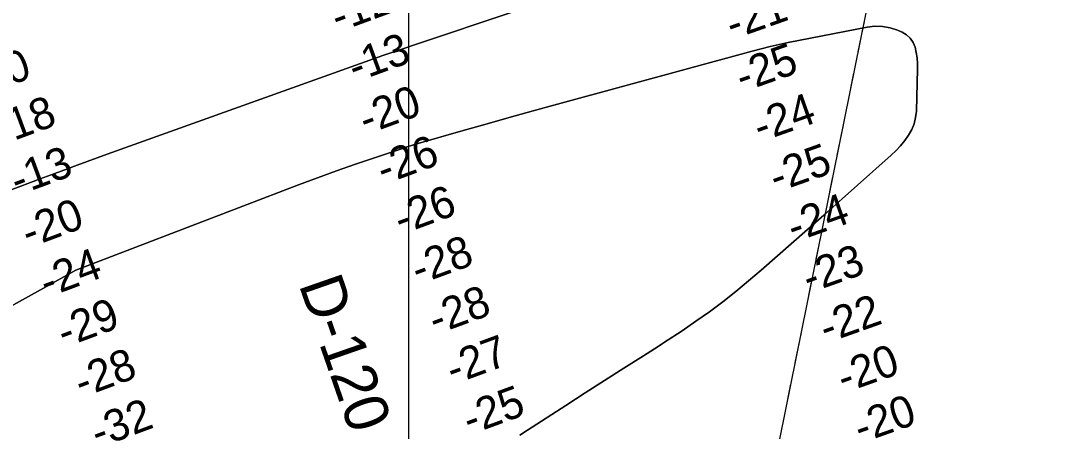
# Model space of a CAD drawing. Extents: x 3245246 to 3283090, y 806824 to 832173.
# Drawn here: x 3259157 to 3261130, y 819294 to 820069 of the extents above; entities that cross this region are included whole.
import ezdxf

# ---------------------------------------------------------------- set-up
doc = ezdxf.new("R2010")
doc.units = 0
for name, color, linetype in [('V-GRID-MAJR', 7, 'Continuous'), ('V-RIVR-FERY', 7, 'Continuous'), ('V-RIVR-RANG', 7, 'Continuous'), ('V-RIVR-RANG-IDEN', 7, 'Continuous'), ('V-TOPO-DPTH', 7, 'Continuous'), ('V-TOPO-MINR', 7, 'Continuous')]:
    doc.layers.add(name, color=color, linetype=linetype)

msp = doc.modelspace()

# ---------------------------------------------------------------- linework, layer by layer
at = {"layer": 'V-GRID-MAJR'}
msp.add_spline([(3259886.4, 812208.7), (3259889.9, 818267.9), (3259893.4, 824330.1), (3259897, 830392.4), (3259897, 830395.5)], degree=3, dxfattribs=at)
at = {"layer": 'V-RIVR-FERY'}
for points in [[(3260522.1, 818934), (3261392, 823224.9)], [(3260740.5, 820011), (3260752, 820068.2)], [(3260720.6, 819913.1), (3260732.2, 819970.3)], [(3260700.8, 819815.2), (3260712.3, 819872.4)], [(3260680.9, 819717.3), (3260692.5, 819774.4)], [(3260661.1, 819619.4), (3260672.6, 819676.5)], [(3260641.2, 819521.5), (3260652.8, 819578.6)], [(3260621.4, 819423.6), (3260632.9, 819480.7)], [(3260601.5, 819325.7), (3260613.1, 819382.8)]]:
    msp.add_lwpolyline(points, dxfattribs=at)
at = {"layer": 'V-TOPO-DPTH'}
for points in [[(3260457.7, 820210.7), (3259841.5, 820003.5), (3259320.2, 819817.3), (3259301.4, 819810.5), (3259282.6, 819803.7), (3259263.9, 819796.8), (3259245.1, 819789.8), (3259221.5, 819780.9), (3259214.6, 819778.3), (3259207.7, 819775.7), (3259200.8, 819773.2), (3259193.9, 819770.6), (3259134, 819748.5)], [(3259134, 819748.5), (3259193.9, 819770.6), (3259200.8, 819773.2), (3259207.7, 819775.7), (3259214.6, 819778.3), (3259221.5, 819780.9), (3259245.1, 819789.8), (3259263.9, 819796.8), (3259282.6, 819803.7), (3259301.4, 819810.5), (3259320.2, 819817.3), (3259841.5, 820003.5), (3260457.7, 820210.7)], [(3260838.8, 820036.6), (3260831.7, 820042.8), (3260823.2, 820047.9), (3260814.7, 820051.5), (3260800.7, 820056), (3260786.5, 820058.8), (3260772, 820059), (3260757.3, 820057.4), (3260608.1, 820028.1), (3260590.9, 820024.6), (3260573.8, 820020.8), (3260556.7, 820016.6), (3260539.8, 820012.1), (3260171.6, 819911.7), (3260125.9, 819899.1), (3260080.2, 819886.4), (3260034.6, 819873.6), (3259989, 819860.6), (3259918.9, 819840.6), (3259908.4, 819837.5), (3259897.9, 819834.3), (3259887.5, 819831.1), (3259877.1, 819827.7), (3259825.6, 819810.7), (3259789.6, 819798.5), (3259753.7, 819786), (3259718, 819773), (3259682.4, 819759.6), (3259261.3, 819598.2), (3258908.3, 819402.7)], [(3258908.3, 819402.7), (3259261.3, 819598.2), (3259682.4, 819759.6), (3259718, 819773), (3259753.7, 819786), (3259789.6, 819798.5), (3259825.6, 819810.7), (3259877.1, 819827.7), (3259887.5, 819831.1), (3259897.9, 819834.3), (3259908.4, 819837.5), (3259918.9, 819840.6), (3259989, 819860.6), (3260034.6, 819873.6), (3260080.2, 819886.4), (3260125.9, 819899.1), (3260171.6, 819911.7), (3260539.8, 820012.1), (3260556.7, 820016.6), (3260573.8, 820020.8), (3260590.9, 820024.6), (3260608.1, 820028.1), (3260757.3, 820057.4), (3260772, 820059), (3260786.5, 820058.8), (3260800.7, 820056), (3260814.7, 820051.5), (3260823.2, 820047.9), (3260831.7, 820042.8), (3260838.8, 820036.6)], [(3260100.7, 819286.7), (3260114.8, 819296.4), (3260187.3, 819343), (3260224, 819366.5), (3260260.7, 819389.9), (3260297.5, 819413.3), (3260334.3, 819436.5), (3260354.9, 819449.5), (3260381.3, 819466.5), (3260407.5, 819483.8), (3260433.3, 819501.7), (3260458.9, 819519.9), (3260484.1, 819538.7), (3260508.9, 819557.9), (3260533.2, 819577.9), (3260557, 819598.3), (3260675.1, 819702), (3260802.9, 819815.8), (3260811.9, 819824.4), (3260820.4, 819833.4), (3260828.2, 819843.1), (3260835.5, 819853.1), (3260841.4, 819863.8), (3260846.1, 819874.9), (3260848.8, 819886.7), (3260850.2, 819898.8), (3260852.5, 819978.4), (3260852.4, 819988.8), (3260851.6, 819999.2), (3260850, 820009.4), (3260847.8, 820019.5), (3260844, 820028.6), (3260838.8, 820036.6)], [(3260838.8, 820036.6), (3260844, 820028.6), (3260847.8, 820019.5), (3260850, 820009.4), (3260851.6, 819999.2), (3260852.4, 819988.8), (3260852.5, 819978.4), (3260850.2, 819898.8), (3260848.8, 819886.7), (3260846.1, 819874.9), (3260841.4, 819863.8), (3260835.5, 819853.1), (3260828.2, 819843.1), (3260820.4, 819833.4), (3260811.9, 819824.4), (3260802.9, 819815.8), (3260675.1, 819702), (3260557, 819598.3), (3260533.2, 819577.9), (3260508.9, 819557.9), (3260484.1, 819538.7), (3260458.9, 819519.9), (3260433.3, 819501.7), (3260407.5, 819483.8), (3260381.3, 819466.5), (3260354.9, 819449.5), (3260334.3, 819436.5), (3260297.5, 819413.3), (3260260.7, 819389.9), (3260224, 819366.5), (3260187.3, 819343), (3260114.8, 819296.4), (3260100.7, 819286.7)]]:
    msp.add_lwpolyline(points, dxfattribs=at)
at = {"layer": 'V-TOPO-MINR'}
for points in [[(3260457.7, 820210.7), (3259841.5, 820003.5), (3259320.2, 819817.3), (3259301.4, 819810.5), (3259282.6, 819803.7), (3259263.9, 819796.8), (3259245.1, 819789.8), (3259221.5, 819780.9), (3259214.6, 819778.3), (3259207.7, 819775.7), (3259200.8, 819773.2), (3259193.9, 819770.6), (3259134, 819748.5)], [(3260838.8, 820036.6), (3260831.7, 820042.8), (3260823.2, 820047.9), (3260814.7, 820051.5), (3260800.7, 820056), (3260786.5, 820058.8), (3260772, 820059), (3260757.3, 820057.4), (3260608.1, 820028.1), (3260590.9, 820024.6), (3260573.8, 820020.8), (3260556.7, 820016.6), (3260539.8, 820012.1), (3260171.6, 819911.7), (3260125.9, 819899.1), (3260080.2, 819886.4), (3260034.6, 819873.6), (3259989, 819860.6), (3259918.9, 819840.6), (3259908.4, 819837.5), (3259897.9, 819834.3), (3259887.5, 819831.1), (3259877.1, 819827.7), (3259825.6, 819810.7), (3259789.6, 819798.5), (3259753.7, 819786), (3259718, 819773), (3259682.4, 819759.6), (3259261.3, 819598.2), (3258908.3, 819402.7)], [(3260100.7, 819286.7), (3260114.8, 819296.4), (3260187.3, 819343), (3260224, 819366.5), (3260260.7, 819389.9), (3260297.5, 819413.3), (3260334.3, 819436.5), (3260354.9, 819449.5), (3260381.3, 819466.5), (3260407.5, 819483.8), (3260433.3, 819501.7), (3260458.9, 819519.9), (3260484.1, 819538.7), (3260508.9, 819557.9), (3260533.2, 819577.9), (3260557, 819598.3), (3260675.1, 819702), (3260802.9, 819815.8), (3260811.9, 819824.4), (3260820.4, 819833.4), (3260828.2, 819843.1), (3260835.5, 819853.1), (3260841.4, 819863.8), (3260846.1, 819874.9), (3260848.8, 819886.7), (3260850.2, 819898.8), (3260852.5, 819978.4), (3260852.4, 819988.8), (3260851.6, 819999.2), (3260850, 820009.4), (3260847.8, 820019.5), (3260844, 820028.6), (3260838.8, 820036.6)]]:
    msp.add_lwpolyline(points, dxfattribs=at)

# ---------------------------------------------------------------- texts
at = {"layer": 'V-RIVR-RANG'}
for s, rotation, p in [('-12', 20.2107, (3259756.5, 820047)), ('-21', 19.5537, (3260502.4, 820033.2)), ('-13', 20.2107, (3259788.9, 819952.3)), ('-20', 20.3915, (3259072, 819922.4)), ('-25', 19.5537, (3260521.2, 819933.8)), ('-20', 20.2107, (3259809.5, 819853.4)), ('-18', 20.3915, (3259119.6, 819833.4)), ('-24', 19.5537, (3260554.6, 819839.5)), ('-26', 20.2107, (3259843, 819759.2)), ('-25', 19.5537, (3260584.9, 819744.2)), ('-13', 20.3915, (3259150.6, 819738.3)), ('-26', 20.2107, (3259875.8, 819664.7)), ('-24', 19.5537, (3260618.3, 819650)), ('-20', 20.3915, (3259171.7, 819639.5)), ('-28', 20.2107, (3259908.2, 819570.1)), ('-24', 20.3915, (3259205.8, 819545.5)), ('-23', 19.5537, (3260647.2, 819554.1)), ('-28', 20.2107, (3259941, 819475.6)), ('-29', 20.3915, (3259239.1, 819451.2)), ('-22', 19.5537, (3260679.6, 819459.5)), ('-27', 20.2107, (3259974.2, 819381.3)), ('-28', 20.3915, (3259271.6, 819356.6)), ('-20', 19.5537, (3260713, 819365.3)), ('-25', 20.2107, (3260005.7, 819286.4)), ('-20', 19.5537, (3260744.8, 819270.5)), ('-32', 20.3915, (3259302.7, 819261.5))]:
    msp.add_text(s, height=60, rotation=rotation, dxfattribs=at).set_placement(p)
at = {"layer": 'V-RIVR-RANG-IDEN'}
msp.add_text('D-120', height=83, rotation=289.1593, dxfattribs=at).set_placement((3259682.1, 819571.5))

doc.saveas('drawing.dxf')
